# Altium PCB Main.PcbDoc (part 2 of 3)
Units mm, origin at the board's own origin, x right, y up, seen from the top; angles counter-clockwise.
Board outline 160.02 x 109 mm, 4 copper layers (Top Layer, MidLayer1, MidLayer2, Bottom Layer), stack 1.588 mm thick; 321 components, 271 nets, 1178 pads, 515 vias.
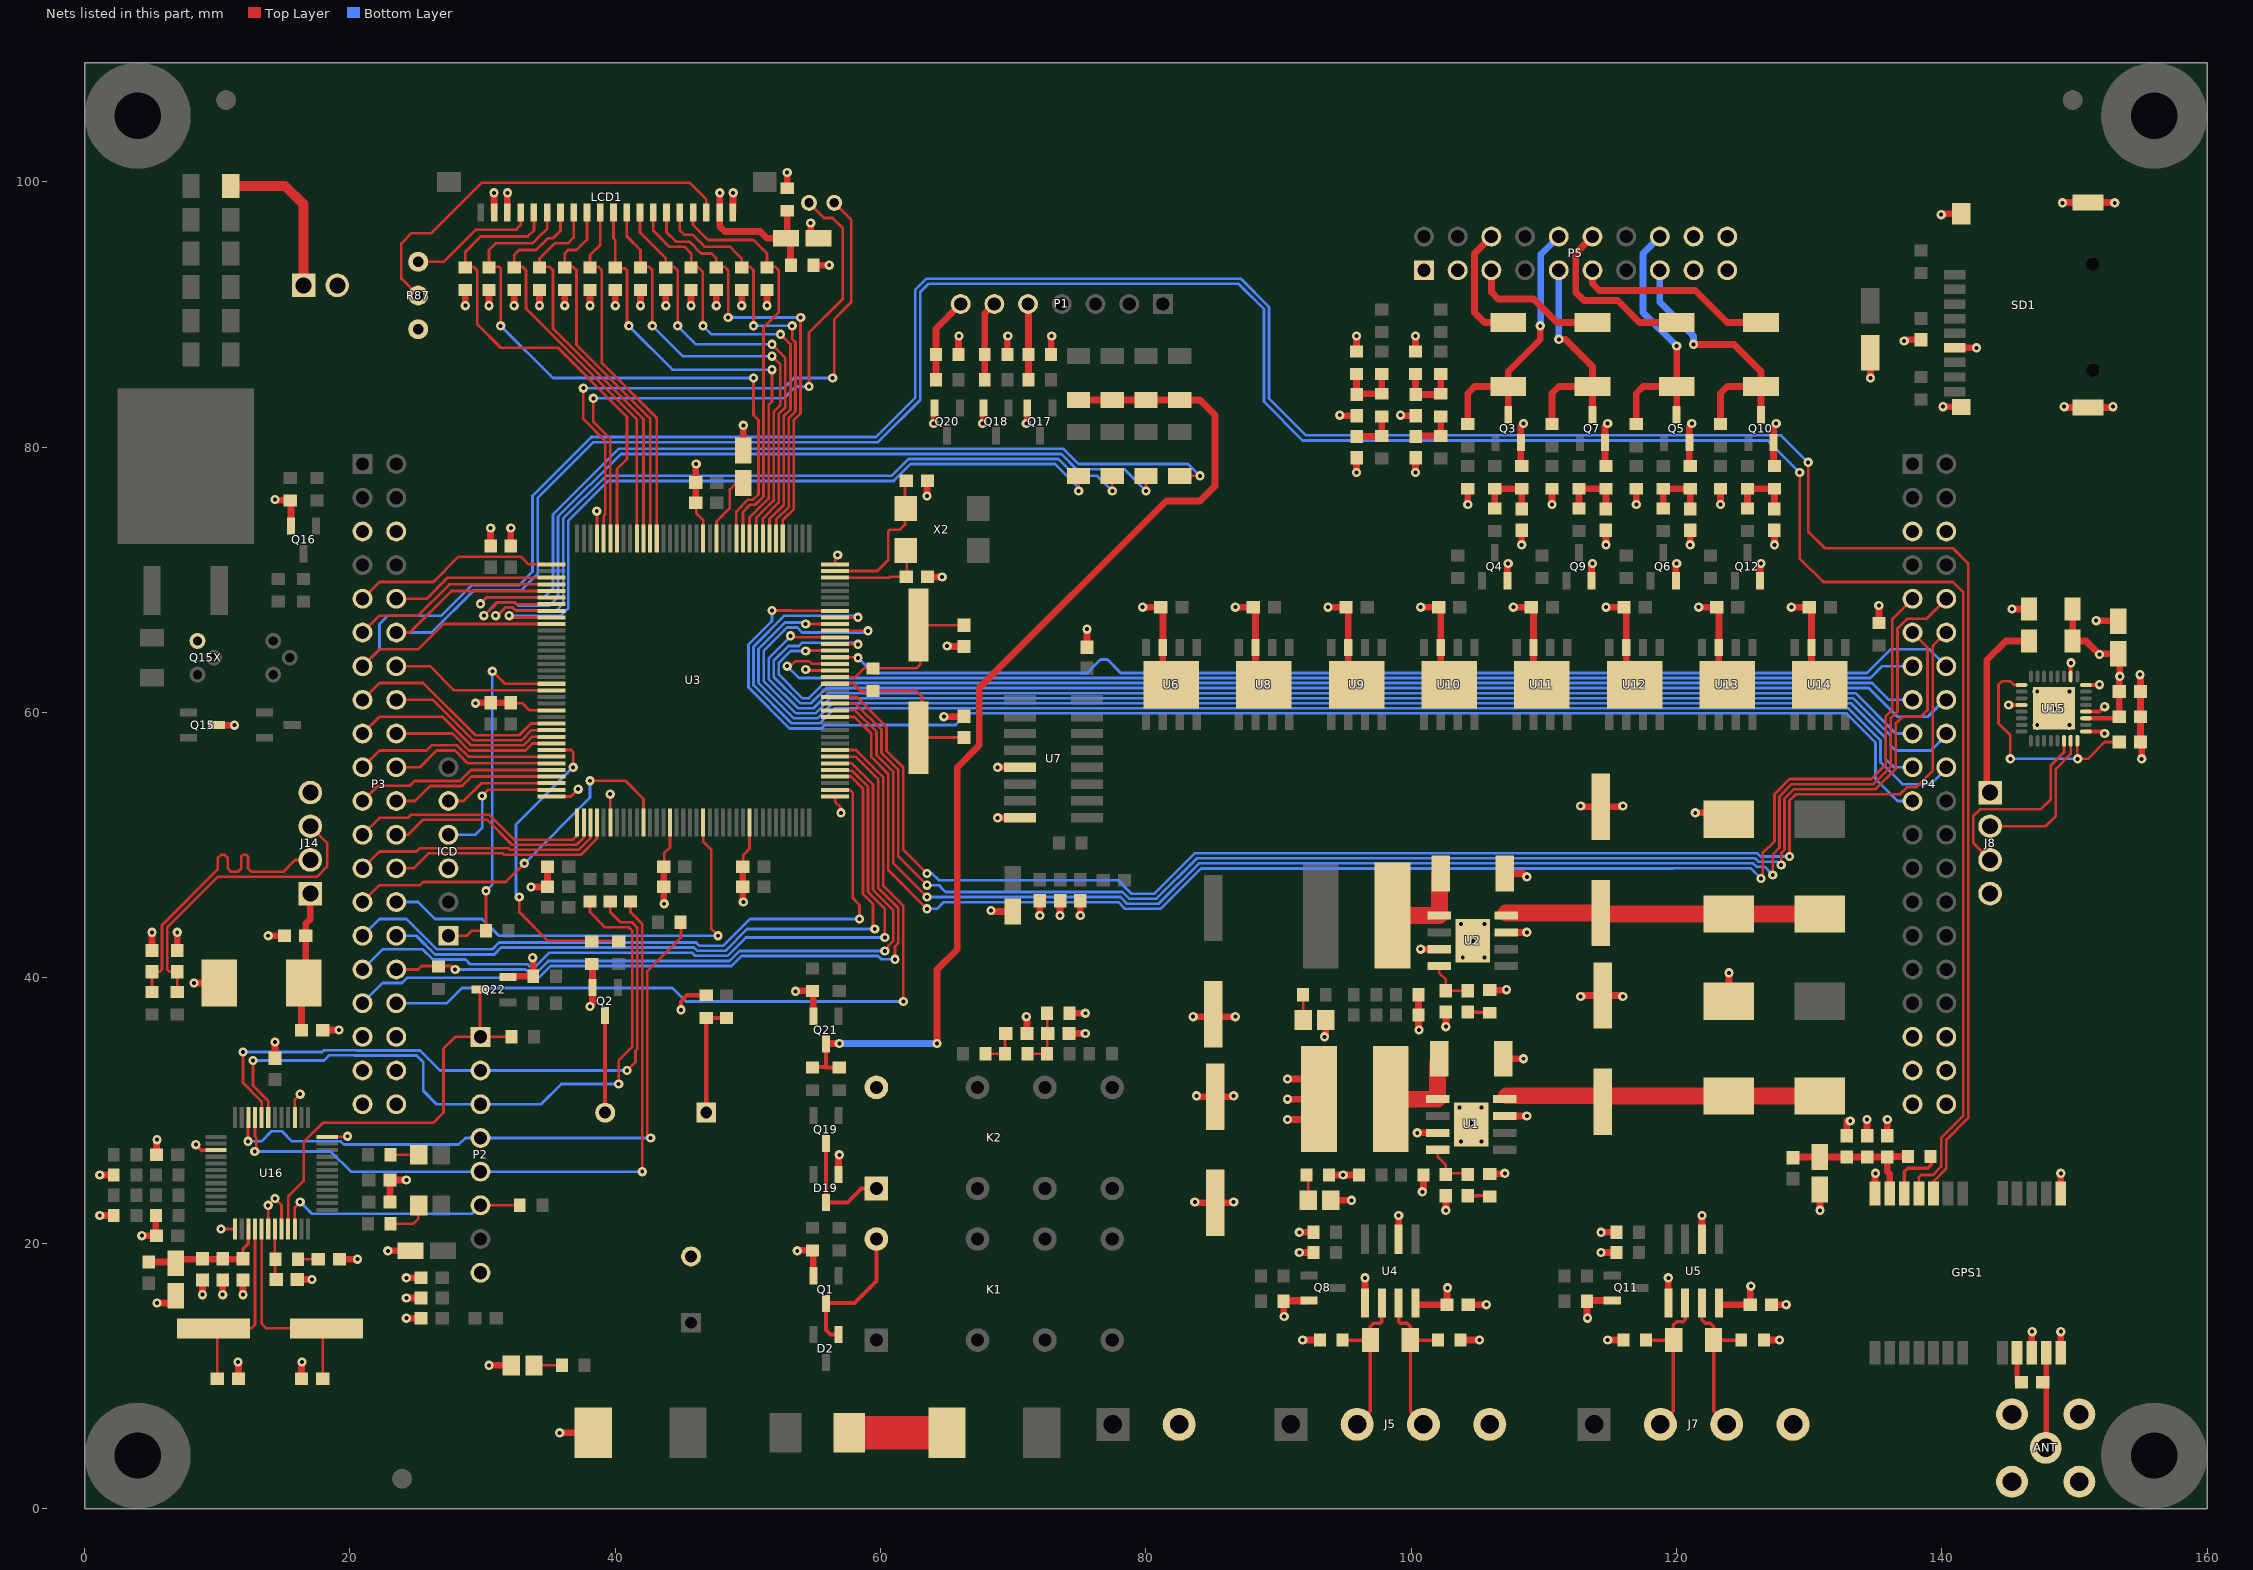
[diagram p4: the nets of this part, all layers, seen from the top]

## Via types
v1: diameter 0.7, hole 0.3, Top Layer to Bottom Layer, tented both sides, 515 vias

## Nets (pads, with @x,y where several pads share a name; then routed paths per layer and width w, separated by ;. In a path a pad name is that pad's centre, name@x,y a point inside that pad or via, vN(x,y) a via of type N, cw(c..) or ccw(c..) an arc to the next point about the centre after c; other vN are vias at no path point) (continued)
+5V: C4.1 C44.1 C46.1 C50.1 C52.1 C55.1 D24.2 L1.2 L7.2 LCD1.2 P3.5 P3.6 P4.5 P4.6 P5.18 P5.20 R2.1 R3.1 R15.1 R47.1 R48.1 R49.1 R60.1 R61.1 R62.1 R75.1 R76.1 R77.1 R78.1 R79.1 R80.1 R81.1 R82.1 R83.1 R84.1 R85.1 R86.1 R87.1 R88.1 U4.8 U5.8 | length 61.8
  Top Layer w0.305: v1(44.958,37.592) 44.958,38.227 45.427,38.696 R15.1@46.863,38.696
  Top Layer w0.5: v1(47.879,99.187) 47.87,99.178 LCD1.2@47.87,97.695 47.87,96.656 48.26,96.266 50.927,96.266 51.435,95.758 52.832,95.758 C50.1@52.959,95.885 ; C50.1@52.959,95.758 C50.1@52.959,95.885 ; C52.1@52.959,97.829 C50.1@52.959,95.885 ; C55.1@53.34,93.726 53.213,93.853 53.213,95.885 C50.1@52.959,95.885
  Top Layer w0.508: L7.2@17.945,36.068 v1(19.177,36.068) ; v1(28.702,90.678) R88.1@28.702,91.86 ; v1(30.48,90.678) R86.1@30.48,91.86 ; v1(32.385,90.678) R85.1@32.385,91.86 ; v1(34.29,90.678) R84.1@34.29,91.86 ; v1(36.195,90.678) R83.1@36.195,91.86 ; v1(38.1,90.678) R82.1@38.1,91.86 ; v1(40.005,90.678) R81.1@40.005,91.86 ; v1(41.91,90.678) R80.1@41.91,91.86 ; v1(43.815,90.678) R79.1@43.815,91.86 ; v1(45.72,90.678) R78.1@45.72,91.86 ; v1(47.625,90.678) R77.1@47.625,91.86 ; v1(49.53,90.678) R76.1@49.53,91.86 ; v1(51.435,90.678) R75.1@51.435,91.86 ; v1(83.82,31.115) 83.884,31.051 C4.1@85.217,31.051 86.55,31.051 v1(86.614,31.115) ; v1(90.678,29.337) 92.202,29.337 93.058,30.193 L1.2@93.058,30.861 ; v1(90.678,30.861) L1.2@93.058,30.861 ; v1(90.678,32.385) 92.583,32.385 93.058,31.91 L1.2@93.058,30.861 ; v1(91.567,19.304) R48.1@92.622,19.304 ; v1(91.567,20.828) R47.1@92.622,20.828 ; v1(91.821,12.7) R49.1@93.13,12.7 ; R2.1@93.814,25.146 v1(94.869,25.146) R3.1@96.051,25.146 ; U4.8@100.457,15.367 C44.1@102.705,15.367 102.705,16.599 v1(102.743,16.637) ; v1(114.3,19.304) R61.1@115.482,19.304 ; v1(114.3,20.828) R60.1@115.482,20.828 ; v1(114.808,12.7) R62.1@115.99,12.7 ; U5.8@123.317,15.367 C46.1@125.565,15.367 125.565,16.726 v1(125.603,16.764) ; v1(145.288,67.811) D24.2@146.563,67.811
+5VUSB: C81.1 C82.1 J14.1 L7.1 | length 10.3
  Top Layer w0.508: L7.1@16.345,36.068 C81.1@16.345,39.154 ; C81.1@16.675,39.154 C82.1@16.675,43.18 16.675,44.107 17.018,44.45 J14.1@17.018,46.228
BUZZER: R17.1 R18.1 U3.29 | length 24.1
  Top Layer w0.203: v1(32.766,46.101) 32.766,44.958 34.925,42.799 R17.1@40.259,42.799 ; U3.29@35.179,57.177 36.676,57.177 36.83,57.023 v1(36.83,55.88)
  Bottom Layer w0.203: v1(32.766,46.101) 32.518,46.349 32.518,51.568 v1(36.83,55.88)
C1: P1.5 R95.1 R100.1 | length 5.7
  Top Layer w0.508: R100.1@71.12,86.995 71.159,86.956 R95.1@71.159,85.09 ; P1.5@71.12,90.805 71.159,90.766 R100.1@71.159,86.995
C2: P1.6 R97.1 R101.1 | length 6
  Top Layer w0.508: R97.1@67.857,85.09 R101.1@67.857,86.995 67.857,90.082 P1.6@68.58,90.805
C3: P1.7 R99.1 R102.1 | length 6.4
  Top Layer w0.508: R99.1@64.174,85.09 R102.1@64.174,86.956 ; R102.1@64.174,86.995 64.174,88.939 P1.7@66.04,90.805
DIGI_ANODE1: D11.2 P5.10 Q3.3 R32.1 | length 20.7
  Top Layer w0.508: R32.1@104.267,81.661 R32.1@104.267,81.749 104.267,84.074 104.775,84.582 D11.2@107.315,84.582 ; Q3.3@107.315,82.423 Q3.3@107.315,82.457 D11.2@107.315,84.582 ; v1(109.728,89.154) 109.728,88.138 107.315,85.725 D11.2@107.315,84.582
  Bottom Layer w0.508: v1(109.728,89.154) 109.766,89.192 109.766,94.526 P5.10@111.125,95.885
DIGI_ANODE2: D12.2 P5.16 Q5.3 R44.1 | length 20.7
  Top Layer w0.508: R44.1@116.967,81.661 R44.1@116.967,81.749 116.967,84.074 117.475,84.582 D12.2@120.015,84.582 ; Q5.3@120.015,82.423 Q5.3@120.015,82.457 D12.2@120.015,84.582 ; v1(120.015,87.63) D12.2@120.015,84.582
  Bottom Layer w0.508: P5.16@118.745,95.885 117.475,94.615 117.475,90.17 v1(120.015,87.63)
DIGI_ANODE3: D13.2 P5.9 Q7.3 R57.1 | length 18.1
  Top Layer w0.508: R57.1@110.617,81.661 R57.1@110.617,81.749 110.617,84.074 111.125,84.582 D13.2@113.665,84.582 ; v1(111.125,88.138) 111.633,88.138 113.665,86.106 D13.2@113.665,84.582 ; Q7.3@113.665,82.423 Q7.3@113.665,82.457 D13.2@113.665,84.582
  Bottom Layer w0.508: v1(111.125,88.138) P5.9@111.125,93.345 P5.9@111.125,93.472
DIGI_ANODE4: D14.2 P5.15 Q10.3 R69.1 | length 21.5
  Top Layer w0.508: v1(121.285,87.757) 124.333,87.757 126.365,85.725 D14.2@126.365,84.582 ; R69.1@123.317,81.661 R69.1@123.317,81.749 123.317,84.074 123.825,84.582 D14.2@126.365,84.582 ; Q10.3@126.365,82.423 Q10.3@126.365,82.457 D14.2@126.365,84.582
  Bottom Layer w0.508: P5.15@118.745,93.345 118.745,90.932 121.285,88.392 v1(121.285,87.757)
DIGI_CATHODE1: D11.1 P5.6 | length 9.1
  Top Layer w0.508: P5.6@106.045,95.885 104.775,94.615 104.775,90.17 105.537,89.408 D11.1@107.315,89.408
DIGI_CATHODE2: D12.1 P5.12 | length 13.3
  Top Layer w0.508: P5.12@113.665,95.885 112.395,94.615 112.395,91.694 113.03,91.059 115.57,91.059 117.221,89.408 D12.1@120.015,89.408
DIGI_CATHODE3: D13.1 P5.5 | length 10.2
  Top Layer w0.508: P5.5@106.045,93.345 106.045,91.694 106.553,91.186 109.22,91.186 110.998,89.408 D13.1@113.665,89.408
DIGI_CATHODE4: D14.1 P5.11 | length 14.9
  Top Layer w0.508: P5.11@113.665,93.345 113.665,92.329 114.173,91.821 121.412,91.821 123.825,89.408 D14.1@126.365,89.408
GND: ANT.2 ANT.3 ANT.4 ANT.5 C1.2 C2.2 C3.2 C4.2 C6.2 C7.2 C9.2 C10.2 C11.2 C12.2 C13.2 C14.2 C15.2 C16.2 C17.2 C18.2 C19.2 C20.2 C21.2 C22.2 C23.2 C24.2 C25.2 C26.2 C27.2 C28.2 C29.2 C30.2 C31.2 C32.2 C33.2 C34.2 C35.2 C36.2 C37.2 C38.2 C39.2 C40.2 C41.2 C42.2 C43.2 C44.2 C45.2 C46.2 C47.2 C48.2 C49.2 C50.2 C51.2 C52.2 C53.2 C54.2 C55.2 C57.2 C58.2 C61.2 C62.2 C64.2 C65.2 C66.2 C68.2 C69.2 C70.2 C71.2 C72.2 C73.2 C74.2 C75.2 C76.2 C77.2 C78.2 C79.2 C80.2 C81.2 C82.2 C83.2 C84.2 C85.2 C86.2 C87.2 C88.2 C89.2 C90.2 D4.2 D6.2 D7.2 D9.2 D10.2 D19.1 GPS1.10 GPS1.12 GPS1.13 GPS1.24 ICD.3 J5.4 J7.4 J8.4 J11.2 J14.4 K2.16 LCD1.1 LCD1.18 LCD1.19 LED1.1 LED2.1 LED3.1 P2.8 P3.35 P3.36 P3.37 P3.38 P3.39 P3.40 P4.35 P4.36 P4.37 P4.38 P4.39 P4.40 P5.1 P5.3 P5.17 P5.19 Q1.2 Q2.2 Q3.2 Q4.2 Q5.2 Q6.2 Q7.2 Q8.2 Q9.2 Q10.2 Q11.2 Q12.2 Q15.3 Q15X.1 Q16.2 Q17.2 Q18.2 Q20.2 Q21.2 Q22.2 R4.2 R5.2 R7.2 R11.2 R12.2 R13.2 R18.2 R24.2 R27.2 R34.2 R35.2 R40.2 R43.2 R46.2 R54.2 R55.2 R56.2 R59.2 R66.2 R68.2 R71.2 R72.2 R73.2 R94.2 R100.2 R101.2 R102.2 R104.2 R107.2 R115.2 R116.2 R117.2 SD1.6 SD1.10 SD1.11 SD1.12 SD1.13 U1.3 U1.7 U1.9 U2.3 U2.7 U2.9 U3.23 U3.36 U3.42 U3.51 U3.63 U3.73 U3.92 U3.108 U3.125 U3.141 U4.2 U4.5 U5.2 U5.5 U6.7 U6.9 U7.5 U7.8 U8.7 U8.9 U9.7 U9.9 U10.7 U10.9 U11.7 U11.9 U12.7 U12.9 U13.7 U13.9 U14.7 U14.9 U15.4 U15.17 U15.20 U15.24 U15.26 U15.33 U16.1 U16.6 U16.8 U16.24 U16.27 U16.39 VIN.2 | length 354.8
  Top Layer w0.203: v1(10.287,21.082) 10.296,21.073 U16.1@11.347,21.073 ; v1(13.843,22.86) 13.846,22.857 U16.6@13.846,21.073 ; v1(14.351,23.368) 14.846,22.873 U16.8@14.846,21.073 ; U16.27@15.846,29.473 15.846,30.832 v1(16.256,31.242) ; U16.24@18.296,28.022 19.767,28.022 v1(19.812,28.067) ; C20.2@32.131,60.706 33.02,60.706 33.55,60.176 U3.23@35.179,60.176 ; U3.36@35.179,53.678 36.66,53.678 v1(37.211,54.229) ; v1(35.814,5.715) v1@35.941,5.715 ; v1(38.608,75.184) 38.631,75.161 U3.141@38.631,73.126 ; v1(39.624,53.848) 39.631,53.841 U3.42@39.631,51.726 ; C24.2@43.688,48.387 43.688,49.403 44.129,49.844 U3.51@44.129,51.726 ; C28.2@46.101,75.819 46.101,75.057 46.629,74.529 U3.125@46.629,73.126 ; C26.2@49.657,48.26 49.657,49.276 50.128,49.747 U3.63@50.128,51.726 ; v1(54.356,63.246) 54.426,63.176 U3.92@56.579,63.176 ; U3.73@56.579,53.678 56.579,53.276 57.023,52.832 v1(57.023,52.451) ; U3.108@56.579,71.174 56.579,71.692 v1(56.769,71.882)
  Top Layer w0.254: v1(8.382,27.432) 8.792,27.022 U16.39@9.896,27.022
  Top Layer w0.305: v1(145.034,60.579) 145.038,60.575 U15.4@146.013,60.575 ; U15.26@149.713,62.725 149.713,63.734 v1(149.733,63.754) ; U15.17@150.863,58.575 152.118,58.575 v1(152.273,58.42) ; U15.20@150.863,60.075 151.896,60.075 v1(152.273,60.452) ; U15.24@150.863,62.075 151.864,62.075 v1(151.892,62.103)
  Top Layer w0.508: v1(1.143,22.098) R117.2@2.198,22.098 ; v1(1.143,25.146) R116.2@2.198,25.146 ; v1(4.318,20.574) 5.334,20.574 5.373,20.613 R115.2@5.373,22.098 ; C78.2@5.08,42.075 v1(5.08,43.434) ; C76.2@5.423,26.67 5.423,27.775 v1(5.461,27.813) ; v1(5.461,15.494) 6.858,15.494 C69.2@6.858,16.047 ; C79.2@6.985,42.075 v1(6.985,43.434) ; v1(8.255,39.624) C81.2@10.16,39.624 ; v1(8.89,16.129) C72.2@8.89,17.234 ; Q15.3@9.94,59.055 v1(11.303,59.055) ; v1(10.414,16.129) C71.2@10.414,17.234 ; v1(11.557,11.049) 11.595,11.011 C84.2@11.595,9.779 ; v1(11.938,16.129) C70.2@11.938,17.234 ; v1(13.843,43.18) C82.2@15.075,43.18 ; C75.2@14.351,33.947 v1(14.351,35.179) ; v1(14.351,76.073) 14.412,76.012 15.56,76.012 Q16.2@15.56,74.075 ; C80.2@16.04,17.272 v1(17.145,17.272) ; C85.2@16.345,9.779 16.345,11.011 v1(16.383,11.049) ; C83.2@19.215,18.796 v1(20.574,18.796) ; v1(22.86,19.431) C14.2@24.556,19.431 ; C74.2@22.987,24.765 23.025,24.727 C77.2@23.025,23.114 ; C74.2@23.025,24.765 v1(24.257,24.765) ; v1(24.257,14.351) C15.2@25.362,14.351 ; v1(24.257,15.875) C16.2@25.362,15.875 ; v1(24.257,17.399) C17.2@25.362,17.399 ; v1(29.464,60.706) 29.502,60.744 C21.2@30.607,60.744 ; v1(30.48,10.795) LED1.1@32.17,10.795 ; C19.2@30.607,72.555 v1(30.607,73.914) ; C21.2@30.696,60.744 C20.2@32.131,60.744 ; v1(30.861,99.187) 30.87,99.178 LCD1.19@30.87,97.695 ; LCD1.18@31.87,97.695 31.87,99.18 v1(31.877,99.187) ; Q22.2@31.877,40.132 R107.2@33.821,40.132 33.821,41.49 v1(33.782,41.529) ; C18.2@32.131,72.555 v1(32.131,73.914) ; v1(33.655,46.863) C22.2@34.887,46.863 ; C22.2@34.887,46.901 C23.2@34.887,48.387 ; v1@35.941,5.715 D4.2@38.34,5.715 ; v1(38.1,37.846) 38.293,38.039 Q2.2@38.293,39.277 R18.2@38.293,40.96 ; C25.2@43.65,46.863 43.65,45.631 v1(43.688,45.593) ; C25.2@43.65,46.901 C24.2@43.65,48.387 ; C28.2@46.063,75.819 C29.2@46.063,77.305 ; C29.2@46.063,77.343 46.063,78.702 v1(46.101,78.74) ; LCD1.1@48.87,97.695 48.87,99.162 v1(48.895,99.187) ; C27.2@49.619,46.863 49.619,45.758 v1(49.657,45.72) ; C27.2@49.619,46.901 C26.2@49.619,48.387 ; C30.2@49.657,79.756 v1(49.657,81.661) ; C52.2@52.959,99.529 v1(52.959,100.711) ; v1(53.594,38.989) 53.633,39.028 R104.2@54.864,39.028 ; v1(53.721,19.431) 53.76,19.47 R7.2@54.864,19.47 ; v1(54.737,96.901) 54.737,95.758 C50.2@55.327,95.758 ; Q1.2@54.93,17.56 R7.2@54.93,19.492 ; Q21.2@54.93,37.118 R104.2@54.93,39.055 ; C55.2@54.952,93.726 v1(56.134,93.726) ; D19.1@56.83,25.18 56.83,26.604 v1(56.896,26.67) ; v1(63.5,76.327) 63.5,77.432 C34.2@63.538,77.47 ; C33.2@63.538,70.231 v1(64.643,70.231) ; v1(64.008,81.788) 64.074,81.854 Q20.2@64.074,82.965 ; v1(64.77,59.69) 65.405,59.69 ; v1(65.024,65.024) 65.062,64.986 C32.2@66.294,64.986 ; 65.443,59.728 65.405,59.69 ; R102.2@65.874,86.995 65.874,88.353 v1(65.913,88.392) ; C31.2@66.294,59.69 65.405,59.69 ; v1(67.691,81.788) 67.757,81.854 Q18.2@67.757,82.965 ; v1(68.326,45.085) 68.408,45.003 C10.2@69.977,45.003 ; v1(68.834,52.07) 68.839,52.075 U7.8@70.5,52.075 ; v1(68.834,55.88) 68.839,55.885 U7.5@70.5,55.885 ; R101.2@69.557,86.995 69.557,88.353 v1(69.596,88.392) ; v1(70.993,37.084) 71.031,37.046 C36.2@71.031,35.814 ; v1(70.993,81.788) 71.059,81.854 Q17.2@71.059,82.965 ; v1(72.009,44.704) C13.2@72.009,45.809 ; R100.2@72.859,86.995 72.859,88.353 v1(72.898,88.392) ; v1(73.533,44.704) C12.2@73.533,45.809 ; C35.2@74.206,35.814 v1(75.438,35.814) ; R24.2@74.256,37.338 v1(75.438,37.338) ; v1(75.057,44.704) C11.2@75.057,45.809 ; C51.2@75.565,64.935 v1(75.565,66.294) ; v1(79.756,67.945) C48.2@81.115,67.945 ; U6.7@81.28,64.897 81.28,62.738 U6.9@81.915,62.103 ; U6.7@81.285,65.201 C48.2@81.285,67.813 ; v1(83.566,37.084) 84.899,37.084 C7.2@85.09,37.275 85.407,37.275 85.598,37.084 v1(86.741,37.084) ; v1(83.693,23.114) 83.756,23.051 C4.2@85.217,23.051 86.551,23.051 v1(86.614,23.114) ; v1(86.741,67.945) C49.2@88.1,67.945 88.265,67.78 U8.7@88.265,64.897 88.265,62.738 U8.9@88.9,62.103 ; v1(90.424,14.478) 90.385,14.517 R56.2@90.385,15.621 Q8.2@92.202,15.621 ; R56.2@90.49,15.687 Q8.2@92.295,15.687 ; v1(93.472,35.56) 93.56,35.648 LED3.1@93.56,36.83 ; v1(93.726,67.945) 95.25,67.945 95.25,65.206 U9.7@95.255,65.201 ; LED2.1@93.941,23.241 v1(95.504,23.241) ; v1(94.615,82.423) 94.653,82.385 C38.2@95.885,82.385 ; U9.7@95.25,64.897 95.25,62.865 U9.9@95.885,62.23 ; v1(95.885,78.105) C39.2@95.885,79.21 ; R34.2@95.885,87.21 v1(95.885,88.392) ; U4.5@96.52,15.507 v1(96.52,17.399) ; U4.2@99.06,20.307 v1(99.06,22.098) ; v1(99.187,82.423) 99.225,82.385 C40.2@100.33,82.385 ; v1(100.33,78.105) C41.2@100.33,79.21 ; R40.2@100.33,87.21 v1(100.33,88.392) ; v1(100.457,28.321) U1.3@101.994,28.321 ; R12.2@100.545,38.647 R13.2@100.545,37.211 100.545,36.107 v1(100.584,36.068) ; v1(100.711,42.164) U2.3@102.121,42.164 ; v1(100.711,67.945) 102.235,67.945 102.235,65.206 U10.7@102.24,65.201 ; v1(100.838,23.876) 100.926,23.964 R5.2@100.926,25.146 ; U10.7@102.235,64.897 102.235,62.738 U10.9@102.87,62.103 ; v1(102.616,22.479) C6.2@102.616,23.584 ; v1(102.616,36.322) C9.2@102.616,37.427 ; v1(103.632,30.226) U1.9@104.521,29.337 ; R54.2@103.72,12.7 v1(105.156,12.7) ; v1(103.759,27.686) U1.9@104.521,28.448 ; v1(103.759,44.069) 103.759,43.688 v1(104.648,42.799) ; v1(103.886,41.529) 104.648,42.291 U2.9@104.648,42.418 ; v1(104.267,75.692) R35.2@104.267,76.874 ; C44.2@104.305,15.367 v1(105.664,15.367) ; v1(105.283,27.686) U1.9@104.521,28.448 ; v1(105.283,30.226) 104.521,29.464 U1.9@104.521,29.337 ; v1(105.537,41.529) U2.9@104.648,42.418 ; v1(105.537,44.069) 105.537,43.688 v1(104.648,42.799) ; R4.2@105.918,25.234 107.022,25.234 v1(107.061,25.273) ; R11.2@105.918,39.077 107.149,39.077 v1(107.188,39.116) ; D6.2@106.934,33.909 v1(108.458,33.909) ; U1.7@107.048,29.591 v1(108.712,29.591) ; D10.2@107.061,47.879 108.458,47.879 v1(108.712,47.625) ; U2.7@107.175,43.434 v1(108.712,43.434) ; Q4.2@107.249,69.943 107.249,71.181 v1(107.315,71.247) ; v1(107.696,67.945) 109.22,67.945 109.22,65.206 U11.7@109.225,65.201 ; R27.2@108.265,78.552 Q3.2@108.265,80.357 108.265,81.595 v1(108.458,81.788) ; v1(108.331,72.644) C37.2@108.331,73.749 ; U11.7@109.22,64.897 109.22,62.738 U11.9@109.855,62.103 ; v1(110.617,75.692) R59.2@110.617,76.874 ; v1(112.776,38.608) 112.839,38.671 C3.2@114.427,38.671 115.888,38.671 v1(115.951,38.608) ; v1(112.776,52.959) 112.84,52.895 C2.2@114.3,52.895 115.887,52.895 v1(115.951,52.959) ; R71.2@113.245,15.621 113.245,14.39 v1(113.284,14.351) ; R71.2@113.345,15.687 Q11.2@115.155,15.687 ; Q9.2@113.599,69.943 113.599,71.181 v1(113.665,71.247) ; R55.2@114.615,78.552 Q7.2@114.615,80.357 114.615,81.595 v1(114.808,81.788) ; v1(114.681,67.945) C58.2@116.04,67.945 ; v1(114.681,72.644) C43.2@114.681,73.749 ; U12.7@116.205,64.897 116.205,62.738 U12.9@116.84,62.103 ; U12.7@116.21,65.201 C58.2@116.21,67.813 ; v1(116.967,75.692) R46.2@116.967,76.874 ; U5.5@119.38,15.507 v1(119.38,17.399) ; Q6.2@119.949,69.943 119.949,71.181 v1(120.015,71.247) ; R43.2@120.965,78.552 Q5.2@120.965,80.357 120.965,81.595 v1(121.158,81.788) ; v1(121.031,72.644) C42.2@121.031,73.749 ; v1(121.412,52.451) 123.458,52.451 D9.2@123.952,51.957 ; v1(121.666,67.945) C61.2@123.025,67.945 ; U5.2@121.92,20.307 v1(121.92,22.098) ; U13.7@123.19,64.897 123.19,62.865 U13.9@123.825,62.23 ; U13.7@123.195,65.201 C61.2@123.195,67.813 ; v1(123.317,75.692) R72.2@123.317,76.874 ; D7.2@123.952,38.241 v1(123.952,40.386) ; Q12.2@126.299,69.943 126.299,71.181 v1(126.365,71.247) ; R68.2@126.58,12.7 v1(127.762,12.7) ; C46.2@127.165,15.367 v1(128.27,15.367) ; R66.2@127.315,78.552 Q10.2@127.315,80.357 127.315,81.595 v1(127.508,81.788) ; v1(127.381,72.644) C45.2@127.381,73.749 ; v1(128.651,67.945) C62.2@130.01,67.945 130.175,67.78 U14.7@130.175,65.282 ; U14.7@130.18,65.201 U14.7@130.175,65.282 ; v1(130.81,22.479) C86.2@130.81,24.048 ; U14.9@130.81,62.23 130.175,62.865 U14.7@130.175,64.897 U14.7@130.175,65.282 ; C89.2@132.842,28.105 132.842,29.21 v1(133.096,29.21) ; C88.2@134.366,28.105 v1(134.366,29.337) ; v1(134.62,85.217) C47.2@134.62,87.122 ; GPS1.24@134.971,23.749 134.971,25.243 v1(135.001,25.273) ; R73.2@135.255,66.763 v1(135.255,68.072) ; C87.2@135.89,28.105 v1(135.89,29.337) ; v1(137.16,88.011) 137.249,88.1 C90.2@138.43,88.1 ; v1(139.954,97.536) 140.017,97.599 SD1.11@141.47,97.599 ; v1(140.081,83.058) 140.09,83.049 SD1.10@141.47,83.049 ; SD1.6@140.97,87.499 142.617,87.499 v1(142.621,87.503) ; GPS1.10@146.771,11.749 146.771,13.294 v1(146.812,13.335) ; v1(147.193,59.055) v1(148.463,60.325) ; v1(147.193,61.595) v1(148.463,60.325) ; GPS1.12@148.971,11.749 v1(148.971,13.335) ; GPS1.13@148.971,23.749 v1(148.971,25.273) ; v1(149.098,98.425) 149.122,98.449 SD1.12@151.02,98.449 153.011,98.449 v1(153.035,98.425) ; v1(149.225,83.058) 149.284,82.999 SD1.13@151.02,82.999 152.849,82.999 v1(152.908,83.058) ; v1(149.606,59.055) 149.606,59.182 v1(148.463,60.325) ; v1(149.606,61.595) 148.463,60.452 v1(148.463,60.325) ; v1(151.638,66.929) 153.244,66.929 C64.2@153.289,66.884 ; v1(154.94,62.865) 154.978,62.827 C66.2@154.978,61.595 ; C68.2@154.978,57.785 155.067,57.696 v1(155.067,56.515) ; C68.2@154.978,57.823 C65.2@154.978,59.69 C66.2@154.978,61.43 ; U1.9@104.521,28.448 U1.9@104.521,28.956 v1(104.521,29.083) U1.9@104.521,29.337 ; U2.9@104.648,42.418 v1(104.648,42.799)
ICD_NMCLR: ICD.1 R14.2 U3.19 | length 27.5
  Top Layer w0.203: ICD.1@27.432,43.18 28.829,43.18 29.21,43.561 R14.2@30.226,43.561 ; R14.2@30.265,43.561 v1(30.265,46.57) ; v1(30.734,63.119) 31.677,62.176 U3.19@35.179,62.176
  Bottom Layer w0.203: v1(30.265,46.57) 30.734,47.039 v1(30.734,63.119)
IDC_PGC: ICD.5 U3.34 | length 8.3
  Top Layer w0.203: ICD.5@27.432,53.34 28.575,53.34 29.913,54.678 U3.34@35.179,54.678
IDC_PGD: ICD.4 U3.35 | length 10.6
  Top Layer w0.203: v1(29.972,53.721) 29.96,53.733 30.404,54.178 U3.35@35.179,54.178
  Bottom Layer w0.203: ICD.4@27.432,50.8 29.464,50.8 29.972,51.308 v1(29.972,53.721)
NetANT_1: ANT.1 GPS1.11 L8.1 | length 7.2
  Top Layer w0.381: ANT.1@147.828,4.572 147.871,4.615 GPS1.11@147.871,11.749
NetBUZ1_1: BUZ1.1 R15.2 R16.2 | length 8.3
  Top Layer w0.305: BUZ1.1@46.863,29.845 R15.2@46.863,36.996 47.967,36.996 R16.2@48.006,36.957
NetBUZ1_2: BUZ1.2 Q2.3 | length 7.3
  Top Layer w0.305: BUZ1.2@39.243,29.845 Q2.3@39.243,37.177
NetC2_1: C2.1 D8.1 D9.1 U2.8 | length 23.4
  Top Layer w1.27: U2.8@107.125,44.895 C2.1@114.3,44.895 ; C2.1@114.54,44.817 D9.1@123.952,44.817 D8.1@130.81,44.817
NetC3_1: C3.1 D5.1 D7.1 U1.8 | length 23.8
  Top Layer w1.27: U1.8@107.188,31.115 113.983,31.115 C3.1@114.427,30.671 ; C3.1@114.441,31.101 D7.1@123.952,31.101 D5.1@130.81,31.101
NetC5_1: C5.1 C6.1 U1.4 | length 3.9
  Top Layer w0.2: U1.4@101.994,27.051 101.994,26.53 102.616,25.908 C6.1@102.616,25.184 102.616,25.146 102.743,25.273 C5.1@104.267,25.273
NetC5_2: C5.2 R4.1 | length 1.7
  Top Layer w0.254: C5.2@104.267,23.584 R4.1@106.007,23.584
NetC8_1: C8.1 C9.1 U2.4 | length 3.7
  Top Layer w0.2: U2.4@102.108,40.894 102.108,40.386 102.616,39.878 102.616,39.116 102.705,39.027 C8.1@104.267,39.027
NetC8_2: C8.2 R11.1 | length 1.6
  Top Layer w0.254: C8.2@104.267,37.427 R11.1@105.829,37.427
NetC30_1: C30.1 U3.123 | length 5.2
  Top Layer w0.203: U3.123@47.629,73.126 47.629,74.395 48.006,74.772 48.006,74.803 48.268,75.065 48.279,75.065 48.641,75.427 48.641,76.835 49.149,77.343 C30.1@49.53,77.343
NetC31_1: C31.1 R19.1 U3.90 X1.1 | length 13
  Top Layer w0.203: U3.90@56.579,62.176 57.966,62.176 58.547,61.595 R19.1@59.563,61.595 ; R19.1@59.436,61.634 62.699,61.634 63.119,61.214 X1.1@63.119,58.674 ; X1.1@63.284,58.128 C31.1@66.294,58.128 C31.1@66.675,58.128
NetC32_1: C32.1 R19.2 U3.91 X1.2 | length 13.4
  Top Layer w0.203: U3.91@56.579,62.676 58.104,62.676 58.801,63.373 R19.2@59.436,63.373 ; R19.2@59.436,63.334 62.699,63.334 62.992,63.627 62.992,66.548 63.03,66.586 C32.1@66.294,66.586 C32.1@66.675,66.586
NetC33_1: C33.1 U3.106 X2.1 | length 7.5
  Top Layer w0.203: U3.106@56.579,70.174 60.649,70.174 60.706,70.231 C33.1@61.938,70.231 61.976,70.231 61.976,72.136 X2.1@62.103,72.263
NetC34_1: C34.1 U3.107 X2.4 | length 11.5
  Top Layer w0.203: U3.107@56.579,70.674 59.752,70.674 60.579,71.501 60.579,73.66 60.706,73.787 61.468,73.787 61.849,74.168 61.849,77.47 C34.1@61.976,77.597
NetC35_1: C35.1 R21.2 R22.1 R24.1 | length 4.2
  Top Layer w0.203: R22.1@71.12,34.29 R21.2@72.556,34.29 72.556,35.648 C35.1@72.517,35.687 ; C35.1@72.556,36.029 R24.1@72.556,37.338
NetC36_1: C36.1 R22.2 R23.1 | length 3
  Top Layer w0.203: R23.1@67.818,34.29 R23.1@67.906,34.29 R22.2@69.381,34.29 C36.1@69.381,35.726
NetC37_1: C37.1 R25.2 R26.1 R27.1 | length 4.7
  Top Layer w0.508: R26.1@106.299,75.565 R25.2@106.299,76.874 ; R25.2@106.514,76.874 R27.1@108.331,76.874 C37.1@108.331,75.349
NetC38_1: C38.1 R29.2 R30.1 R34.1 | length 4.8
  Top Layer w0.508: C38.1@95.885,83.985 R34.1@95.885,85.471 ; C38.1@96.051,84.035 R30.1@97.79,84.035 R29.2@97.79,85.51 R29.2@97.79,85.598 ; R30.1@97.79,83.985 R30.1@97.828,83.985
NetC39_1: C39.1 R30.2 R31.1 | length 3.3
  Top Layer w0.508: C39.1@95.885,80.81 R31.1@97.701,80.81 ; R31.1@97.701,80.86 R31.1@97.701,81.026 ; R31.1@97.79,81.026 R30.2@97.79,82.335
NetC40_1: C40.1 R37.2 R38.1 R40.1 | length 5
  Top Layer w0.508: R40.1@100.33,85.598 R40.1@100.33,85.51 C40.1@100.33,83.985 R38.1@102.146,83.985 ; R38.1@102.235,84.035 R37.2@102.235,85.51 R37.2@102.235,85.598
NetC41_1: C41.1 R38.2 R39.1 | length 3.3
  Top Layer w0.508: C41.1@100.242,80.86 R39.1@102.235,80.86 ; R39.1@102.235,81.026 R38.2@102.235,82.335
NetC42_1: C42.1 R41.2 R42.1 R43.1 | length 4.7
  Top Layer w0.508: R42.1@118.999,75.565 R41.2@118.999,76.874 ; R41.2@119.214,76.874 R43.1@121.031,76.874 C42.1@121.031,75.349
NetC43_1: C43.1 R51.2 R52.1 R55.1 | length 4.7
  Top Layer w0.508: R52.1@112.649,75.565 R51.2@112.649,76.874 ; R51.2@112.864,76.874 R55.1@114.681,76.874 C43.1@114.681,75.349
NetC45_1: C45.1 R63.2 R64.1 R66.1 | length 4.7
  Top Layer w0.508: R64.1@125.349,75.565 R63.2@125.349,76.874 ; R63.2@125.564,76.874 R66.1@127.381,76.874 C45.1@127.381,75.349
NetC64_1: C64.1 C65.1 C66.1 D24.1 D25.1 U15.19 | length 13.4
  Top Layer w0.305: U15.19@150.863,59.575 C65.1@153.174,59.575
  Top Layer w0.5: v1(151.892,64.389) 151.937,64.434 C64.1@153.289,64.434 153.416,64.307 v1(153.416,62.738) 153.378,62.7 C66.1@153.378,61.595 C65.1@153.378,59.69
  Top Layer w0.508: D24.1@149.863,67.811 149.863,65.409 D25.1@149.859,65.405 150.876,65.405 v1(151.892,64.389)
NetC68_1: C68.1 U15.1 U15.16 | length 17.9
  Top Layer w0.203: v1(145.161,56.515) 145.161,58.293 144.272,59.182 144.272,62.103 144.526,62.357 145.161,62.357 145.443,62.075 U15.1@146.013,62.075 ; v1@150.213,56.67 U15.16@150.213,57.875 ; v1(150.241,56.515) 151.003,56.515 152.273,57.785 C68.1@153.378,57.785
  Bottom Layer w0.203: v1(145.161,56.515) v1(150.241,56.515)
NetC69_1: C69.1 C70.1 C71.1 C72.1 L6.2 U16.3 | length 9.7
  Top Layer w0.254: C70.1@11.938,18.796 C70.1@11.938,18.834 11.938,19.558 12.347,19.967 U16.3@12.347,21.073
  Top Layer w0.508: L6.2@4.826,18.58 6.82,18.58 6.858,18.542 7.112,18.796 10.414,18.796 C70.1@11.938,18.796
NetC78_1: C78.1 J14.2 R111.1 | length 23
  Top Layer w0.203: R111.1@5.08,38.95 C78.1@5.08,40.475 5.677,40.475 5.842,40.64 5.842,43.973 10.033,48.164 10.033,49.022 10.287,49.276 10.541,49.276 10.795,49.022 10.795,48.26 11.049,48.006 11.557,48.006 11.811,48.26 11.811,49.149 11.938,49.276 12.192,49.276 12.319,49.149 12.319,48.26 12.573,48.006 14.986,48.006 15.875,48.895 J14.2@17.018,48.895
NetC79_1: C79.1 J14.3 R113.1 | length 23.1
  Top Layer w0.203: R113.1@6.985,38.95 C79.1@6.985,40.475 6.388,40.475 6.223,40.64 6.223,43.815 10.033,47.625 17.526,47.625 18.288,48.387 18.288,50.165 J14.3@17.018,51.435
NetC80_1: C80.1 R118.1 U16.7 | length 3.8
  Top Layer w0.203: U16.7@14.346,21.073 14.346,18.801 14.351,18.796 C80.1@14.351,17.272
NetC83_1: C83.1 R118.2 | length 1.5
  Top Layer w0.203: R118.2@16.129,18.796 C83.1@17.615,18.796
NetC84_1: C84.1 U16.4 X3.1 | length 14
  Top Layer w0.203: X3.1@9.779,13.589 12.573,13.589 12.847,13.863 U16.4@12.847,21.073 ; C84.1@9.995,9.779 X3.1@9.995,13.373
NetC85_1: C85.1 U16.5 X3.2 | length 15.8
  Top Layer w0.203: 13.335,13.97 13.346,13.981 U16.5@13.346,21.073 ; 13.346,13.959 13.716,13.589 X3.2@18.22,13.589 X3.2@18.288,13.589 ; C85.1@17.945,9.779 X3.2@17.945,13.373
NetC86_1: C86.1 C87.1 C88.1 C89.1 GPS1.23 L9.1 R123.2 | length 11.3
  Top Layer w0.508: L9.1@128.86,26.498 C86.1@130.81,26.498 ; C86.1@130.772,26.505 C89.1@132.842,26.505 ; C89.1@132.931,26.505 C88.1@134.366,26.505 ; C88.1@134.582,26.505 C87.1@135.89,26.505 ; GPS1.23@136.071,23.749 136.071,25.219 135.89,25.4 C87.1@135.89,26.505 ; R123.2@137.541,26.416 137.414,26.543 135.89,26.543 C87.1@135.89,26.505
NetD1_1: D1.1 D3.1 | length 7.2
  Top Layer w2.54: D3.1@57.785,5.715 D1.1@65.01,5.715
NetD2_1: D2.1 K1.16 Q1.3 | length 10.8
  Top Layer w0.305: D2.1@56.83,13.115 56.227,13.115 55.88,13.462 Q1.3@55.88,15.46 55.88,15.494 58.039,15.494 59.69,17.145 K1.16@59.69,20.32
NetD6_1: D6.1 L1.1 U1.1 | length 6.2
  Top Layer w1.27: L1.1@98.425,30.861 L1.1@98.458,30.861 U1.1@101.994,30.861 D6.1@101.994,33.541
NetD10_1: D10.1 L2.1 U2.1 | length 6.5
  Top Layer w1.27: L2.1@98.679,44.704 U2.1@102.121,44.704 D10.1@102.121,47.739
NetD15_2: D15.2 D17.2 D20.2 D22.2 Q21.3 R96.2 R98.2 | length 80.6
  Top Layer w0.305: R96.2@54.737,33.274 55.88,33.274 Q21.3@55.88,35.018 ; 55.88,33.235 R98.2@56.896,33.235
  Top Layer w0.508: Q21.3@55.88,35.052 v1(56.896,35.052) ; v1(64.262,35.052) 64.262,40.64 65.786,42.164 65.786,55.88 67.437,57.531 67.437,61.849 81.534,75.946 84.074,75.946 85.217,77.089 85.217,82.423 84.074,83.566 D20.2@77.47,83.567 ; D22.2@74.93,83.567 D20.2@77.47,83.567 ; D20.2@77.471,83.567 D20.2@77.47,83.567
  Bottom Layer w0.508: v1(56.896,35.052) v1(64.262,35.052)
NetD16_2: D16.2 U3.6 | length 70.3
  Top Layer w0.203: v1(29.845,68.199) 30.347,68.701 35.152,68.701 U3.6@35.179,68.674 ; D16.2@82.55,77.852 v1(84.074,77.851) v1(84.074,77.851)
  Bottom Layer w0.203: v1(29.845,68.199) 30.347,68.701 34.671,68.701 35.312,69.342 35.312,74.933 40.262,79.883 73.787,79.883 74.93,78.74 83.185,78.74 v1(84.074,77.851)
NetD18_2: D18.2 U3.7 | length 66.6
  Top Layer w0.203: v1(30.099,67.31) 30.359,67.57 ; 30.359,67.571 31.108,68.32 32.423,68.32 32.569,68.174 U3.7@35.179,68.174 ; v1(80.01,76.708) D18.2@80.01,77.852
  Bottom Layer w0.203: v1(30.099,67.31) 31.108,68.32 32.423,68.32 32.671,68.072 35.052,68.072 35.693,68.713 35.693,74.775 40.419,79.502 73.629,79.502 74.788,78.344 78.374,78.344 v1(80.01,76.708)
NetD19_3: D19.3 K2.1 Q19.3 | length 8.6
  Top Layer w0.305: Q19.3@55.88,27.432 D19.3@55.88,23.08 57.497,23.08 58.547,24.13 K2.1@59.69,24.13
NetD21_2: D21.2 U3.8 | length 62
  Top Layer w0.203: v1(30.988,67.31) 31.115,67.31 31.375,67.57 ; 31.375,67.571 31.743,67.939 32.265,67.939 32.53,67.674 U3.8@35.179,67.674 ; v1(77.47,76.708) D21.2@77.47,77.852
  Bottom Layer w0.203: v1(30.988,67.31) 31.114,67.31 31.743,67.939 32.265,67.939 32.513,67.691 35.56,67.691 36.074,68.205 36.074,74.617 39.302,77.845 60.831,77.845 62.107,79.121 73.406,79.121 74.676,77.851 76.327,77.851 v1(77.47,76.708)
NetD23_2: D23.2 U3.9 | length 56.9
  Top Layer w0.203: v1(32.004,67.31) 32.139,67.175 U3.9@35.179,67.175 ; v1(74.93,76.708) D23.2@74.93,77.852
  Bottom Layer w0.203: v1(32.004,67.31) 35.921,67.31 36.455,67.843 36.455,74.46 39.459,77.464 60.989,77.464 62.265,78.74 73.152,78.74 74.168,77.724 ; 74.168,77.718 74.174,77.718 74.93,76.962 v1(74.93,76.708)
NetD25_2: D25.2 J8.1 | length 13.9
  Top Layer w0.508: J8.1@143.637,53.975 143.383,54.229 143.383,63.959 144.829,65.405 D25.2@146.559,65.405
NetGPS1_9: GPS1.9 L8.2 | length 2.2
  Top Layer w0.381: L8.2@145.671,9.527 GPS1.9@145.671,11.749
NetGPS1_20: GPS1.20 P3.13 U3.10 | length 222.5
  Top Layer w0.203: P3.13@20.955,63.5 22.225,64.77 25.146,64.77 27.051,66.675 U3.10@35.179,66.675 ; v1(129.921,78.867) 129.921,73.66 131.191,72.39 140.843,72.39 141.986,71.247 141.986,29.433 140.335,27.782 140.335,25.623 139.371,24.659 GPS1.20@139.371,23.749
  Bottom Layer w0.203: P3.13@20.955,63.5 22.225,64.77 22.225,66.675 22.86,67.31 26.893,67.31 29.179,69.596 32.735,69.596 33.767,70.627 33.767,76.342 38.196,80.772 59.659,80.772 62.611,83.724 62.611,91.852 63.469,92.71 87.153,92.71 89.281,90.582 89.281,83.693 92.075,80.899 127.889,80.899 v1(129.921,78.867)
NetGPS1_21: GPS1.21 P3.12 U3.5 | length 214.8
  Top Layer w0.203: P3.12@23.495,66.04 24.511,66.04 27.645,69.174 U3.5@35.179,69.174 ; v1(129.286,78.105) 129.286,71.628 131.064,69.85 140.843,69.85 141.605,69.088 141.605,29.591 139.954,27.94 139.954,25.781 139.319,25.146 138.43,25.146 138.271,24.987 GPS1.21@138.271,23.749
  Bottom Layer w0.203: P3.12@23.495,66.04 26.162,66.04 29.337,69.215 32.893,69.215 34.163,70.485 34.163,76.2 38.354,80.391 59.817,80.391 62.992,83.566 62.992,91.694 63.627,92.329 86.995,92.329 88.9,90.424 88.9,83.439 91.821,80.518 126.873,80.518 v1(129.286,78.105)
NetGPS1_22: GPS1.22 R123.1 | length 4.5
  Top Layer w0.254: GPS1.22@137.171,23.749 137.171,25.389 137.436,25.654 138.938,25.654 139.192,25.908 R123.1@139.192,26.543
NetJ5_2: J5.2 R49.2 R50.1 U4.6 | length 12.1
  Top Layer w0.254: R49.2@94.869,12.7 96.901,12.7 96.901,7.326 J5.2@95.925,6.35 ; R50.1@96.901,12.827 96.901,13.716 97.155,13.97 97.663,13.97 97.79,14.097 U4.6@97.79,15.507
NetJ5_3: J5.3 R50.2 R54.1 U4.7 | length 12.3
  Top Layer w0.254: U4.7@99.06,15.507 99.06,14.097 99.187,13.97 99.695,13.97 99.949,13.716 R50.2@99.949,12.7 ; J5.3@100.925,6.35 99.949,7.326 R50.2@99.949,12.7 ; R54.1@101.981,12.7 R50.2@99.949,12.7
NetJ7_2: J7.2 R62.2 R65.1 U5.6 | length 12.3
  Top Layer w0.254: R62.2@117.729,12.7 R65.1@119.761,12.7 ; J7.2@118.785,6.35 119.761,7.326 R65.1@119.761,12.7 ; U5.6@120.65,15.507 120.65,14.224 120.523,14.097 120.015,14.097 119.761,13.843 R65.1@119.761,12.7
NetJ7_3: J7.3 R65.2 R68.1 U5.7 | length 12.2
  Top Layer w0.254: U5.7@121.92,15.507 121.92,14.224 122.174,13.97 122.555,13.97 122.809,13.716 R65.2@122.809,12.7 ; J7.3@123.785,6.35 122.809,7.326 R65.2@122.809,12.7 ; R68.1@124.841,12.7 R65.2@122.809,12.7
NetJ8_2: J8.2 U15.15 | length 11.4
  Top Layer w0.203: J8.2@143.637,51.435 147.828,51.435 148.59,52.197 148.59,55.754 149.713,56.877 U15.15@149.713,57.875
NetJ8_3: J8.3 U15.14 | length 15
  Top Layer w0.203: J8.3@143.637,48.895 142.367,50.165 142.367,52.197 142.875,52.705 147.447,52.705 148.209,53.467 148.209,56.007 149.213,57.011 U15.14@149.213,57.875
NetJ11_1: J11.1 R129.2 | length 12.3
  Top Layer w0.762: R129.2@10.922,99.695 R129.2@11.025,99.695 15.113,99.695 16.51,98.298 J11.1@16.51,92.202
NetLCD1_3: LCD1.3 R87.2 | length 30.9
  Top Layer w0.203: R87.2@25.146,91.44 23.876,92.71 23.876,95.377 24.638,96.139 26.162,96.139 29.972,99.949 45.593,99.949 46.87,98.672 LCD1.3@46.87,97.695
NetLCD1_4: LCD1.4 R75.2 U3.119 | length 31
  Top Layer w0.203: LCD1.4@45.87,97.695 45.87,96.751 46.99,95.631 50.419,95.631 51.435,94.615 51.435,93.599 52.07,93.599 52.324,93.345 52.324,90.17 51.181,89.027 51.181,76.296 50.556,75.671 50.174,75.671 49.628,75.124 U3.119@49.628,73.126
NetLCD1_5: LCD1.5 R76.2 U3.114 | length 32.4
  Top Layer w0.203: LCD1.5@44.87,97.695 44.87,96.354 45.212,96.012 45.847,96.012 46.736,95.123 48.641,95.123 49.149,94.615 49.53,94.234 49.53,93.599 50.165,93.599 50.419,93.345 v1(50.419,89.154) ; U3.114@52.127,73.126 52.127,74.548 53.086,75.507 53.086,82.202 53.588,82.705 53.588,87.92 53.34,88.169 v1(53.34,89.154)
  Bottom Layer w0.203: v1(50.419,89.154) v1(53.34,89.154)
NetLCD1_6: LCD1.6 R77.2 U3.113 | length 33.9
  Top Layer w0.203: LCD1.6@43.87,97.695 43.87,96.211 44.577,95.504 45.593,95.504 46.482,94.615 47.244,94.615 47.625,94.234 47.625,93.599 48.26,93.599 48.514,93.345 v1(48.514,89.789) ; U3.113@52.627,73.126 52.627,74.509 53.467,75.349 53.467,82.045 53.969,82.547 53.969,89.783 v1(53.975,89.789)
  Bottom Layer w0.203: v1(48.514,89.789) v1(53.975,89.789)
NetLCD1_7: LCD1.7 R78.2 U3.115 | length 33.5
  Top Layer w0.203: LCD1.7@42.87,97.695 42.87,96.322 44.069,95.123 45.212,95.123 45.72,94.615 45.72,93.599 46.228,93.599 46.609,93.218 v1(46.609,89.154) ; U3.115@51.628,73.126 51.628,74.587 52.705,75.665 52.705,82.36 53.207,82.863 53.207,87.763 v1(52.451,88.519)
  Bottom Layer w0.203: v1(46.609,89.154) 47.244,88.519 v1(52.451,88.519)
NetLCD1_8: LCD1.8 R79.2 U3.116 | length 33.5
  Top Layer w0.203: LCD1.8@41.87,97.695 41.87,96.179 43.815,94.234 43.815,93.599 44.45,93.599 44.704,93.345 v1(44.704,89.154) ; U3.116@51.128,73.126 51.128,74.626 52.324,75.823 52.324,82.518 52.826,83.02 52.826,86.748 v1@51.817,87.757
  Bottom Layer w0.203: v1(44.704,89.154) 46.101,87.757 v1(51.816,87.757)
NetLCD1_9: LCD1.9 R80.2 U3.117 | length 34.4
  Top Layer w0.203: LCD1.9@40.87,97.695 40.87,95.909 41.91,94.869 41.91,93.599 42.545,93.599 42.799,93.345 v1(42.799,89.154) ; U3.117@50.628,73.126 50.628,74.665 51.943,75.98 51.943,82.676 52.445,83.178 52.445,86.239 v1(51.816,86.868)
  Bottom Layer w0.203: v1(42.799,89.154) 45.085,86.868 v1(51.816,86.868)
NetLCD1_10: LCD1.10 R81.2 U3.118 | length 35.1
  Top Layer w0.203: LCD1.10@39.87,97.695 39.87,95.766 40.005,95.631 R81.2@40.005,93.56 40.005,93.472 40.767,93.472 40.894,93.345 40.894,89.281 v1(41.021,89.154) ; U3.118@50.128,73.126 50.128,74.704 51.562,76.138 51.562,83.185 51.816,83.439 v1(51.816,85.852)
  Bottom Layer w0.203: v1(41.021,89.154) 44.323,85.852 v1(51.816,85.852)
NetLCD1_11: LCD1.11 R82.2 U3.132 | length 27.2
  Top Layer w0.203: R82.2@38.1,93.599 38.1,94.488 38.87,95.258 LCD1.11@38.87,97.695 ; R82.2@38.227,93.599 38.735,93.599 38.989,93.345 38.989,86.356 43.13,82.216 U3.132@43.13,73.126
NetLCD1_12: LCD1.12 R83.2 U3.133 | length 28.7
  Top Layer w0.203: LCD1.12@37.87,97.695 37.87,95.655 37.084,94.869 36.449,94.869 36.195,94.615 36.195,93.599 36.83,93.599 37.084,93.345 37.084,87.722 42.63,82.177 U3.133@42.63,73.126
NetLCD1_13: LCD1.13 R84.2 U3.134 | length 30.1
  Top Layer w0.203: R84.2@34.163,93.599 R84.2@34.29,93.599 ; LCD1.13@36.87,97.695 36.87,95.798 36.449,95.377 35.433,95.377 34.29,94.234 R84.2@34.29,93.599 ; U3.134@42.13,73.126 42.13,82.138 35.306,88.962 35.306,93.345 35.052,93.599 R84.2@34.29,93.599
NetLCD1_14: LCD1.14 R85.2 U3.135 | length 31.1
  Top Layer w0.203: R85.2@32.385,93.599 32.385,94.488 32.766,94.869 34.036,94.869 34.925,95.758 35.306,95.758 35.87,96.322 LCD1.14@35.87,97.695 ; R85.2@32.512,93.599 33.02,93.599 33.274,93.345 33.274,90.455 41.63,82.099 U3.135@41.63,73.126
NetLCD1_15: LCD1.15 R86.2 U3.120 | length 46.7
  Top Layer w0.203: v1(31.369,89.154) 31.369,93.472 31.242,93.599 30.48,93.599 30.48,94.869 30.988,95.377 33.751,95.377 34.513,96.139 34.544,96.139 34.87,96.465 LCD1.15@34.87,97.695 ; U3.120@49.128,73.126 49.128,75.163 50.017,76.052 50.398,76.052 50.8,76.454 50.8,82.042 50.419,82.423 v1(50.419,85.217)
  Bottom Layer w0.203: v1(31.369,89.154) 35.306,85.217 v1(50.419,85.217)
NetLCD1_16: LCD1.16 R88.2 U3.138 | length 37.1
  Top Layer w0.203: LCD1.16@33.87,97.695 33.87,96.354 33.401,95.885 29.845,95.885 28.702,94.742 28.702,93.599 29.337,93.599 29.591,93.345 29.591,89.281 31.369,87.503 35.687,87.503 40.894,82.296 40.894,79.121 40.13,78.357 U3.138@40.13,73.126
NetLCD1_17: LCD1.17 R87.3 | length 9.8
  Top Layer w0.203: R87.3@25.146,93.98 27.051,93.98 29.464,96.393 32.512,96.393 32.87,96.751 LCD1.17@32.87,97.695
NetLCD-SPR1_1: LCD-SPR1.1 U3.139 | length 44
  Top Layer w0.203: v1(38.354,83.693) 38.354,81.915 39.631,80.638 U3.139@39.631,73.126 ; v1(54.61,84.582) 54.61,88.646 57.15,91.186 57.15,96.52 56.388,97.282 55.753,97.282 LCD-SPR1.1@54.61,98.425
  Bottom Layer w0.203: v1(38.354,83.693) 52.705,83.693 53.594,84.582 v1(54.61,84.582)
NetLCD-SPR2_1: LCD-SPR2.1 U3.140 | length 45.5
  Top Layer w0.203: v1(37.592,84.455) 37.592,82.138 39.237,80.493 39.237,74.923 39.131,74.817 U3.140@39.131,73.126 ; v1(56.388,85.217) 56.515,85.344 56.515,89.662 57.785,90.932 57.785,97.155 LCD-SPR2.1@56.515,98.425
  Bottom Layer w0.203: v1(37.592,84.455) 52.705,84.455 53.467,85.217 v1(56.388,85.217)
NetLED1_2: LED1.2 R1.2 | length 1.9
  Top Layer w0.203: LED1.2@33.87,10.795 R1.2@35.814,10.795
NetLED2_2: LED2.2 R2.2 | length 1.8
  Top Layer w0.203: LED2.2@92.241,23.241 R2.2@92.241,25.058
NetLED3_2: LED3.2 R8.2 | length 2
  Top Layer w0.203: LED3.2@91.86,36.742 LED3.2@91.86,36.83 R8.2@91.86,38.735
NetLED4_1: LED4.1 R119.2 | length 1.9
  Top Layer w0.203: R119.2@23.241,26.67 LED4.1@25.185,26.67
NetLED5_1: LED5.1 R120.2 | length 3.2
  Top Layer w0.203: R120.2@23.075,21.463 24.765,21.463 25.146,21.844 LED5.1@25.146,22.86
NetP2_1: P2.1 Q22.3 R105.2 U16.9 | length 32.4
  Top Layer w0.203: U16.9@15.346,21.073 15.346,23.516 16.51,24.68 16.51,27.626 17.967,29.083 26.289,29.083 27.051,29.845 27.051,34.671 27.94,35.56 P2.1@29.811,35.56 ; Q22.3@29.811,39.116 P2.1@29.811,35.56 ; R105.2@32.17,35.56 P2.1@29.845,35.56 P2.1@29.811,35.56
NetP2_2: P2.2 R131.1 U16.32 | length 49.5
  Top Layer w0.203: v1@11.938,34.544 v1(11.938,34.417) 11.938,32.1 13.346,30.692 U16.32@13.346,29.473 ; R131.1@39.624,45.72 39.624,44.958 40.386,44.196 41.275,44.196 41.656,43.815 41.656,34.64 41.529,34.513 41.529,33.655 v1(40.894,33.02)
  Bottom Layer w0.203: v1(11.938,34.417) 17.907,34.417 18.034,34.544 20.516,34.544 20.529,34.531 25.286,34.531 26.797,33.02 P2.2@29.845,33.02 ; P2.2@29.972,33.02 v1(40.894,33.02)
NetP2_3: P2.3 R130.1 U16.31 | length 52.2
  Top Layer w0.203: v1(12.7,33.782) 12.7,31.877 13.846,30.731 U16.31@13.846,29.473 ; R130.1@38.1,45.72 38.1,44.958 39.243,43.815 41.021,43.815 41.275,43.561 41.275,34.798 40.259,33.782 v1(40.259,32.004)
  Bottom Layer w0.203: v1(12.7,33.782) 18.034,33.782 18.415,34.163 20.358,34.163 20.371,34.15 25.032,34.15 25.527,33.655 25.527,31.496 26.543,30.48 P2.3@29.718,30.48 ; P2.3@29.972,30.48 34.417,30.48 35.941,32.004 v1(40.259,32.004)
NetP2_4: P2.4 R133.1 U16.34 | length 50.4
  Top Layer w0.203: v1(12.319,27.686) U16.34@12.319,29.337 ; v1(42.672,27.94) 42.418,28.194 42.418,40.513 44.958,43.053 R133.1@44.958,44.196
  Bottom Layer w0.203: v1(12.319,27.686) 13.334,27.686 14.09,28.442 14.895,28.442 15.652,27.686 19.303,27.686 19.551,27.438 28.2,27.438 28.702,27.94 P2.4@29.845,27.94 v1(42.672,27.94)
NetP2_5: P2.5 R132.1 U16.33 | length 53.2
  Top Layer w0.203: v1(12.827,26.924) 12.948,27.045 12.948,27.947 12.847,28.048 U16.33@12.847,29.473 ; R132.1@41.148,45.72 41.148,44.958 42.037,44.069 v1(42.037,25.4)
  Bottom Layer w0.203: v1(12.827,26.924) 18.542,26.924 20.066,25.4 P2.5@29.845,25.4 v1(42.037,25.4)
NetP2_6: P2.6 R108.2 U16.10 | length 19.4
  Top Layer w0.203: U16.10@15.846,21.073 15.846,22.704 v1(16.256,23.114) ; P2.6@29.845,22.86 R108.2@32.805,22.86
  Bottom Layer w0.203: v1(16.256,23.114) 17.145,22.225 29.21,22.225 P2.6@29.845,22.86
NetP3_9: P3.9 U3.1 | length 15.8
  Top Layer w0.203: P3.9@20.955,68.58 22.225,69.85 26.289,69.85 28.194,71.755 32.893,71.755 33.474,71.174 U3.1@35.179,71.174
NetP3_10: P3.10 U3.3 | length 12.3
  Top Layer w0.203: P3.10@23.495,68.58 25.781,68.58 27.375,70.174 U3.3@35.179,70.174
NetP3_11: P3.11 U3.4 | length 15.7
  Top Layer w0.203: P3.11@20.955,66.04 22.225,67.31 25.146,67.31 27.51,69.674 U3.4@35.179,69.674
NetP3_14: P3.14 U3.20 | length 12.4
  Top Layer w0.203: P3.14@23.495,63.5 26.035,63.5 27.859,61.676 U3.20@35.179,61.676
NetP3_15: P3.15 U3.25 | length 16.7
  Top Layer w0.203: P3.15@20.955,60.96 22.225,62.23 25.526,62.23 29.463,58.293 32.766,58.293 33.65,59.177 U3.25@35.179,59.177
NetP3_16: P3.16 U3.26 | length 13.1
  Top Layer w0.203: P3.16@23.622,60.96 26.257,60.96 29.305,57.912 32.924,57.912 33.689,58.677 U3.26@35.179,58.677
NetP3_17: P3.17 U3.27 | length 15.9
  Top Layer w0.203: P3.17@20.955,58.42 22.225,59.69 26.988,59.69 29.147,57.531 33.082,57.531 33.727,58.177 U3.27@35.179,58.177
NetP3_18: P3.18 U3.28 | length 12.4
  Top Layer w0.203: P3.18@23.495,58.42 27.719,58.42 28.989,57.15 33.239,57.15 33.766,57.677 U3.28@35.179,57.677
NetP3_19: P3.19 U3.30 | length 15.1
  Top Layer w0.203: P3.19@21.082,56.007 22.225,57.15 25.781,57.15 26.162,57.531 28.07,57.531 28.923,56.677 U3.30@35.179,56.677
NetP3_20: P3.20 U3.31 | length 12.9
  Top Layer w0.203: P3.20@23.241,56.007 23.32,55.928 P3.20@23.495,55.928 ; P3.20@23.495,55.88 25.273,55.88 26.543,57.15 27.912,57.15 28.884,56.177 U3.31@35.179,56.177
NetP3_21: P3.21 U3.32 | length 15.2
  Top Layer w0.203: P3.21@20.955,53.34 22.098,54.483 24.511,54.483 24.879,54.851 28.308,54.851 29.135,55.678 U3.32@35.179,55.678
NetP3_22: P3.22 U3.33 | length 12.4
  Top Layer w0.203: P3.22@23.495,53.34 24.905,53.34 26.035,54.47 28.466,54.47 29.173,55.178 U3.33@35.179,55.178
NetP3_23: P3.23 U3.37 | length 18.7
  Top Layer w0.203: P3.23@20.955,50.8 22.225,52.07 24.384,52.07 24.625,52.311 30.493,52.311 32.385,50.419 36.83,50.419 37.131,50.72 U3.37@37.131,51.726
NetP3_24: P3.24 U3.38 | length 16.8
  Top Layer w0.203: P3.24@23.495,50.8 24.397,50.8 25.527,51.93 30.335,51.93 32.227,50.038 37.084,50.038 37.631,50.585 U3.38@37.631,51.726
NetP3_25: P3.25 U3.39 | length 19.4
  Top Layer w0.203: P3.25@20.955,48.26 22.225,49.53 25.019,49.53 25.26,49.771 31.955,49.771 32.069,49.657 37.242,49.657 38.131,50.546 U3.39@38.131,51.726
NetP3_26: P3.26 U3.40 | length 17.4
  Top Layer w0.203: P3.26@23.495,48.26 24.778,48.26 25.908,49.39 31.496,49.39 31.61,49.276 37.4,49.276 38.631,50.507 U3.40@38.631,51.726
NetP3_27: P3.27 U3.47 | length 28
  Top Layer w0.203: P3.27@20.955,45.72 22.225,46.99 25.273,46.99 25.514,47.231 31.737,47.231 v1(33.147,48.641) ; v1(38.1,54.864) 40.767,54.864 42.13,53.501 U3.47@42.13,51.726
  Bottom Layer w0.203: v1(33.147,48.641) 38.1,53.594 v1(38.1,54.864)
NetP3_28: P3.28 U3.56 | length 34.3
  Top Layer w0.203: U3.56@46.629,51.726 46.629,50.268 47.244,49.653 47.244,43.688 v1(47.752,43.18)
  Bottom Layer w0.203: P3.28@23.495,45.72 25.146,45.72 26.416,44.45 29.972,44.45 31.242,43.18 v1(47.752,43.18)
NetP3_29: P3.29 U3.74 | length 51.2
  Top Layer w0.203: U3.74@56.579,54.178 57.681,54.178 57.913,53.946 57.913,51.712 ; 57.912,51.711 57.912,46.009 58.42,45.501 v1(58.42,44.45)
  Bottom Layer w0.203: P3.29@20.955,43.18 22.225,44.45 24.268,44.45 26.567,42.151 28.297,42.151 28.31,42.164 30.734,42.164 31.242,42.672 46.1,42.672 46.348,42.424 48.139,42.424 50.165,44.45 v1(58.42,44.45)
NetP3_30: P3.30 U3.76 | length 51.1
  Top Layer w0.203: U3.76@56.579,55.178 57.759,55.178 58.675,54.262 58.675,51.396 58.674,46.324 59.436,45.562 59.436,43.815 v1(59.563,43.688)
  Bottom Layer w0.203: P3.30@23.495,43.18 24.999,43.18 26.409,41.77 30.879,41.77 31.4,42.291 45.942,42.291 46.19,42.043 48.296,42.043 49.942,43.688 v1(59.563,43.688)
NetP3_31: P3.31 U3.77 | length 56.5
  Top Layer w0.203: U3.77@56.579,55.678 56.647,55.609 57.866,55.609 59.056,54.42 59.056,51.238 59.055,46.482 60.325,45.212 v1(60.325,43.053)
  Bottom Layer w0.203: P3.31@20.955,40.64 22.466,42.151 23.921,42.151 23.934,42.164 25.477,42.164 26.251,41.389 28.702,41.389 29.07,41.021 33.4,41.021 33.521,40.9 34.043,40.9 35.053,41.91 45.784,41.91 46.033,41.662 48.454,41.662 49.846,43.053 v1(60.325,43.053)
NetP3_32: P3.32 R92.2 U3.78 | length 54.7
  Top Layer w0.203: P3.32@23.495,40.64 25.146,40.64 25.4,40.894 27.686,40.894 v1(27.94,40.64) ; U3.78@56.579,56.177 57.837,56.177 59.437,54.577 59.437,51.081 ; 59.436,51.08 59.436,46.64 60.954,45.121 60.954,42.792 60.586,42.424 ; v1(60.325,42.037) 60.585,42.297 60.585,42.424
  Bottom Layer w0.203: v1(27.94,40.64) 33.242,40.64 33.363,40.519 34.201,40.519 34.957,41.275 48.606,41.275 49.368,42.037 v1(60.325,42.037)
NetP3_33: P3.33 U3.79 | length 60
  Top Layer w0.203: U3.79@56.579,56.677 58.127,56.677 59.818,54.987 59.818,50.923 ; 59.817,50.922 59.817,46.798 61.335,45.279 61.335,42.634 61.087,42.386 v1(61.087,41.402)
  Bottom Layer w0.203: P3.33@20.955,38.1 22.466,39.611 23.921,39.611 24.32,40.011 34.231,40.011 35.115,40.894 48.764,40.894 49.526,41.656 59.816,41.656 60.064,41.408 61.081,41.408 v1(61.087,41.402)
NetP3_34: P3.34 U3.80 | length 61.1
  Top Layer w0.203: U3.80@56.579,57.177 58.166,57.177 60.199,55.145 60.199,50.765 60.198,46.955 61.716,45.437 v1@61.716,38.233 ; v1(61.722,38.227) v1@61.722,38.233
  Bottom Layer w0.203: P3.34@23.495,38.1 27.305,38.1 28.454,39.249 44.323,39.249 45.345,38.227 v1(61.722,38.227)
NetP4_9: P4.9 U3.85 | length 112.5
  Top Layer w0.203: U3.85@56.579,59.676 58.039,59.676 59.309,58.406 59.309,56.642 60.58,55.371 60.58,50.607 60.579,48.132 v1(63.5,45.212) ; v1(126.365,47.498) 126.492,47.625 126.492,49.403 127.381,50.292 127.381,53.847 128.525,54.991 134.685,54.991 135.763,56.069 135.763,59.721 136.271,60.229 136.271,67.056 P4.9@137.795,68.58
  Bottom Layer w0.203: v1(63.5,45.212) 64.262,45.212 64.764,45.714 77.922,45.714 78.424,45.212 81.118,45.212 84.161,48.254 119.74,48.254 119.745,48.26 125.603,48.26 v1(126.365,47.498)
NetP4_10: P4.10 U3.86 | length 114.1
  Top Layer w0.203: U3.86@56.579,60.176 58.078,60.176 59.69,58.564 59.69,56.8 60.961,55.529 60.961,50.449 ; 60.96,50.449 60.96,48.64 v1(63.5,46.101) ; v1(127.254,47.752) 127.26,47.758 127.26,49.314 127.762,49.816 127.762,53.689 128.683,54.61 134.843,54.61 136.144,55.911 136.144,59.563 136.652,60.071 136.652,66.352 137.369,67.069 138.824,67.069 P4.10@140.335,68.58
  Bottom Layer w0.203: v1(63.5,46.101) 67.426,46.101 67.431,46.095 78.08,46.095 78.582,45.593 80.961,45.593 84.009,48.641 125.761,48.641 126.015,48.387 126.619,48.387 v1(127.254,47.752)
NetP4_11: P4.11 U3.87 | length 110.8
  Top Layer w0.203: U3.87@56.579,60.676 58.166,60.676 58.166,60.627 60.071,58.722 60.071,56.958 61.342,55.687 61.342,49.147 v1(63.5,46.99) ; v1(127.889,48.514) 127.895,48.52 127.895,49.41 128.143,49.658 128.143,53.524 128.848,54.229 135.001,54.229 136.525,55.753 136.525,59.182 137.033,59.69 138.43,59.69 138.925,60.185 138.925,64.91 P4.11@137.795,66.04
  Bottom Layer w0.203: v1(63.5,46.99) 64.389,46.99 64.897,46.482 78.232,46.482 78.74,45.974 80.803,45.974 83.851,49.022 125.919,49.022 126.173,48.768 127.635,48.768 v1(127.889,48.514)
NetP4_12: P4.12 U3.88 | length 110.9
  Top Layer w0.203: U3.88@56.579,61.176 58.205,61.176 60.452,58.929 60.452,57.115 61.723,55.845 61.723,49.656 v1(63.5,47.879) ; v1(128.524,49.149) 128.524,53.366 129.006,53.848 136.848,53.848 137.369,54.369 138.062,54.369 139.306,55.613 139.306,65.011 P4.12@140.335,66.04
  Bottom Layer w0.203: v1(63.5,47.879) 63.881,47.879 64.389,47.371 77.882,47.371 78.898,46.355 80.645,46.355 83.693,49.403 126.076,49.403 126.33,49.149 v1(128.524,49.149)
NetP4_13: P4.13 U3.93 | length 89.4
  Top Layer w0.203: v1(52.959,63.5) 53.213,63.5 53.588,63.875 54.617,63.875 54.817,63.675 U3.93@56.579,63.675
  Bottom Layer w0.203: v1(52.959,63.5) 53.848,62.611 134.62,62.611 135.509,63.5 P4.13@137.795,63.5
NetP4_14: P4.14 U3.94 | length 86.3
  Top Layer w0.203: U3.94@56.579,64.175 58.253,64.175 v1(58.293,64.135)
  Bottom Layer w0.203: v1(58.293,64.135) 59.436,62.992 75.564,62.992 76.574,64.002 77.096,64.002 78.106,62.992 134.366,62.992 136.144,64.77 139.065,64.77 P4.14@140.335,63.5
NetP4_15: P4.15 U3.95 | length 92.7
  Top Layer w0.203: v1(54.356,64.643) 54.388,64.675 U3.95@56.579,64.675
  Bottom Layer w0.203: v1(54.356,64.643) 53.212,64.643 52.33,63.761 52.33,62.858 54.095,61.093 54.617,61.093 55.754,62.23 134.747,62.23 136.017,60.96 P4.15@137.795,60.96
NetP4_16: P4.16 U3.96 | length 101.1
  Top Layer w0.203: U3.96@56.579,65.175 58.269,65.175 v1(58.293,65.151)
  Bottom Layer w0.203: v1(58.293,65.151) 58.172,65.272 54.095,65.272 53.847,65.024 53.054,65.024 51.949,63.919 51.949,62.7 53.937,60.712 54.775,60.712 55.912,61.849 134.493,61.849 136.652,59.69 138.938,59.69 P4.16@140.335,61.087
NetP4_17: P4.17 U3.97 | length 96.2
  Top Layer w0.203: v1(53.213,65.786) 53.324,65.675 U3.97@56.579,65.675
  Bottom Layer w0.203: v1(53.213,65.786) 53.213,65.722 51.568,64.076 51.568,62.543 53.78,60.331 54.932,60.331 56.07,61.468 133.477,61.468 136.525,58.42 P4.17@137.795,58.42
NetP4_18: P4.18 U3.98 | length 106.7
  Top Layer w0.203: U3.98@56.579,66.175 59.047,66.175 v1(59.055,66.167)
  Bottom Layer w0.203: v1(59.055,66.167) 58.934,66.046 54.095,66.046 53.725,66.415 52.952,66.415 51.187,64.65 51.187,62.385 53.622,59.95 55.09,59.95 56.228,61.087 133.319,61.087 136.144,58.262 136.144,57.531 136.525,57.15 139.192,57.15 P4.18@140.335,58.293
NetP4_19: P4.19 U3.99 | length 100.7
  Top Layer w0.203: v1@54.356,66.675 U3.99@56.579,66.675
  Bottom Layer w0.203: v1(54.356,66.675) 54.235,66.796 52.794,66.796 50.806,64.808 50.806,62.227 53.464,59.569 55.248,59.569 56.385,60.706 133.161,60.706 135.763,58.104 135.763,56.515 136.398,55.88 P4.19@137.795,55.88
NetP4_20: P4.20 U3.100 | length 109.1
  Top Layer w0.203: U3.100@56.579,67.175 58.285,67.175 v1(58.293,67.183)
  Bottom Layer w0.203: v1(58.293,67.183) 58.172,67.304 52.764,67.304 50.425,64.965 50.425,62.069 53.306,59.188 55.406,59.188 56.543,60.325 132.969,60.325 135.382,57.912 135.382,56.261 137.033,54.61 139.192,54.61 P4.20@140.462,55.88
NetP4_21: P4.21 U3.101 | length 105.1
  Top Layer w0.203: v1(51.816,67.691) 53.34,67.691 53.357,67.674 U3.101@56.579,67.674
  Bottom Layer w0.203: v1(51.816,67.691) 51.816,66.896 50.044,65.123 50.044,61.911 53.148,58.807 55.564,58.807 55.812,59.055 59.425,59.055 59.43,59.061 65.666,59.061 66.549,59.944 132.811,59.944 135.001,57.754 135.001,54.991 136.652,53.34 P4.21@137.795,53.34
